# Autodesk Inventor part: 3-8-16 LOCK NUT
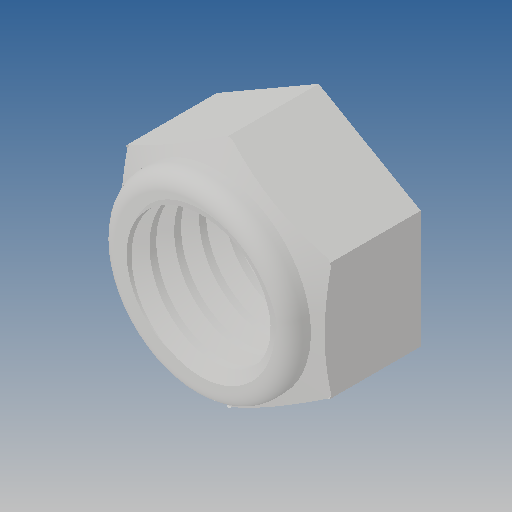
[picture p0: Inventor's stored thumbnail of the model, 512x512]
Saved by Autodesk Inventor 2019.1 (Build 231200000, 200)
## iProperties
Created: 2012-10
Part Number: 3-8-16 LOCK NUT
Material: Ogólny
Document SubType Name: Modeling
Designer: CADENGINEERING4
Density: 1 g/cm^3
Appearance: Domyślna
Author: CADENGINEERING4
Revision Number: ÈÎºÎ
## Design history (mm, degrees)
feature "ÇÐ³ý-É¨Ãè1"
node "Bryła1"
